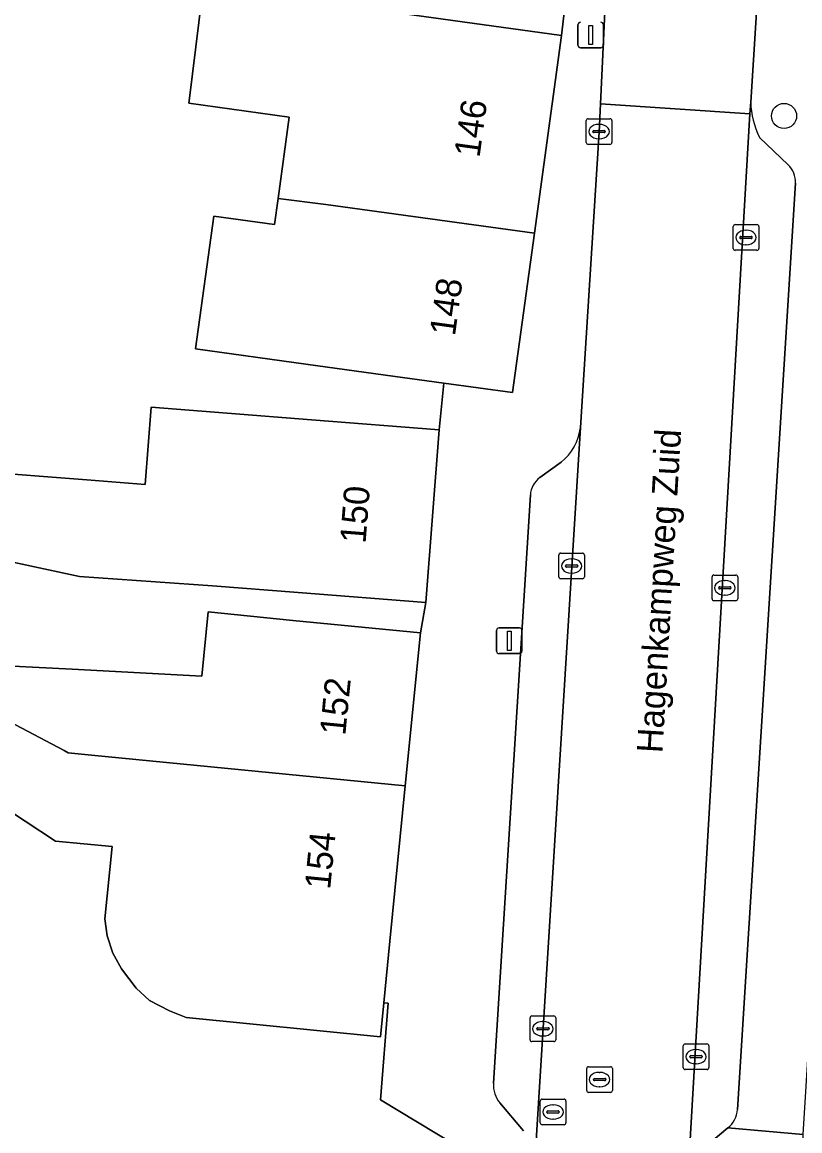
# Model space of a CAD drawing. Extents: x 160102 to 160934, y 382045 to 382923.
# Drawn here: x 160536.3 to 160566.62, y 382542.01 to 382585.21 of the extents above; entities that cross this region are included whole.
import ezdxf

# ---------------------------------------------------------------- set-up
doc = ezdxf.new("R2010")
doc.units = 0
for name, color, linetype in [('IMGEO_Boom', 7, 'Continuous'), ('IMGEO_Brandkraan', 7, 'Continuous'), ('IMGEO_Erf', 7, 'Continuous'), ('IMGEO_Kolk', 7, 'Continuous'), ('IMGEO_Lichtmast', 7, 'Continuous'), ('IMGEO_Openbare_ruimte_label', 7, 'Continuous'), ('IMGEO_Pand', 7, 'Continuous'), ('IMGEO_Pand_nummerreeks', 7, 'Continuous'), ('IMGEO_Parkeervlak_open', 7, 'Continuous'), ('IMGEO_Rijbaan_lokaal_open', 7, 'Continuous'), ('IMGEO_Rioolput', 7, 'Continuous'), ('IMGEO_Voetpad_open', 7, 'Continuous')]:
    doc.layers.add(name, color=color, linetype=linetype)

msp = doc.modelspace()

# ---------------------------------------------------------------- linework, layer by layer
at = {"layer": 'IMGEO_Boom'}
msp.add_circle((160566.008, 382581.561), 0.489, dxfattribs=at)
at = {"layer": 'IMGEO_Brandkraan'}
for p, q in [((160556.501, 382542.322), (160556.501, 382543.174)), ((160556.576, 382543.248), (160557.428, 382543.248)), ((160556.989, 382543.028), (160557.014, 382543.028)), ((160557.502, 382543.174), (160557.502, 382542.322)), ((160556.76, 382542.742), (160556.76, 382542.754)), ((160557.198, 382542.705), (160556.8, 382542.705)), ((160556.803, 382542.791), (160557.201, 382542.791)), ((160557.012, 382542.468), (160556.987, 382542.468)), ((160557.244, 382542.754), (160557.244, 382542.742)), ((160557.428, 382542.248), (160556.576, 382542.248))]:
    msp.add_line(p, q, dxfattribs=at)
for points in [[(160556.501, 382542.322), (160556.501, 382543.174)], [(160556.576, 382543.248), (160557.428, 382543.248)], [(160557.502, 382543.174), (160557.502, 382542.322)], [(160557.428, 382542.248), (160556.576, 382542.248)]]:
    msp.add_lwpolyline(points, dxfattribs=at)
for centre, radius, start, end in [((160556.578, 382543.172), 0.0765, 91.552, 178.448), ((160556.578, 382543.172), 0.0765, 91.552, 178.448), ((160557.426, 382543.172), 0.0765, 1.552, 88.448), ((160557.426, 382543.172), 0.0765, 1.552, 88.448), ((160556.8, 382542.751), 0.0403, 85.8775, 175.7526), ((160556.797, 382542.741), 0.0366, 178.938, 274.7102), ((160557.201, 382542.748), 0.043, 264.8664, 352.4533), ((160557.205, 382542.753), 0.0386, 1.7309, 96.639), ((160556.578, 382542.324), 0.0765, 181.552, 268.448), ((160556.578, 382542.324), 0.0765, 181.552, 268.448), ((160557.426, 382542.324), 0.0765, 271.552, 358.448), ((160557.426, 382542.324), 0.0765, 271.552, 358.448)]:
    msp.add_arc(centre, radius, start, end, dxfattribs=at)
for centre, major_axis, ratio, start_param, end_param in [((160556.988, 382542.748), (-0.387, 0.002), 0.722429, 4.712389, 7.853982), ((160557.013, 382542.748), (-0.39, 0.002), 0.717154, 1.570796, 4.712389)]:
    msp.add_ellipse(centre, major_axis=major_axis, ratio=ratio, start_param=start_param, end_param=end_param, dxfattribs=at)
at = {"layer": 'IMGEO_Erf'}
for points in [[(160534.423, 382567.722), (160538.823, 382567.379), (160541.092, 382567.202), (160541.327, 382570.206), (160544.296, 382569.974), (160547.58, 382569.718), (160552.564, 382569.329), (160552.74, 382571.149), (160550.464, 382571.463), (160547.358, 382571.891), (160543.062, 382572.483), (160543.774, 382577.654), (160546.137, 382577.329), (160546.277, 382578.344), (160546.714, 382581.519), (160542.799, 382582.058), (160542.826, 382582.251), (160544.031, 382592.059)], [(160553.83, 382590.868), (160553.333, 382590.898), (160550.367, 382591.268), (160550.341, 382591.08), (160549.608, 382585.762), (160557.335, 382584.697), (160557.538, 382586.493), (160556.132, 382586.617)], [(160534.372, 382560.203), (160538.255, 382559.998), (160543.303, 382559.732), (160543.549, 382562.231), (160546.852, 382561.905), (160551.827, 382561.414), (160552.04, 382562.601), (160547.056, 382562.989), (160543.727, 382563.248), (160538.538, 382563.615), (160535.938, 382564.173)], [(160554.602, 382540.614), (160550.277, 382543.226), (160550.574, 382546.994), (160550.406, 382547), (160550.275, 382545.677), (160542.701, 382546.424), (160542.048, 382546.688), (160541.272, 382547.092), (160540.742, 382547.567), (160540.177, 382548.324), (160539.842, 382548.94), (160539.612, 382549.61), (160539.529, 382550.277), (160539.806, 382553.087), (160537.595, 382553.305), (160532.862, 382556.422)]]:
    msp.add_lwpolyline(points, dxfattribs=at)
at = {"layer": 'IMGEO_Kolk'}
for p, q in [((160558.294, 382580.526), (160558.294, 382581.378)), ((160558.369, 382581.452), (160559.221, 382581.452)), ((160559.295, 382581.378), (160559.295, 382580.526)), ((160558.553, 382580.946), (160558.553, 382580.958)), ((160558.991, 382580.909), (160558.593, 382580.909)), ((160558.596, 382580.995), (160558.994, 382580.995)), ((160558.782, 382581.232), (160558.807, 382581.232)), ((160559.037, 382580.958), (160559.037, 382580.946)), ((160558.805, 382580.672), (160558.78, 382580.672)), ((160559.221, 382580.452), (160558.369, 382580.452)), ((160564.024, 382576.398), (160564.024, 382577.25)), ((160564.099, 382577.324), (160564.951, 382577.324)), ((160564.512, 382577.104), (160564.537, 382577.104)), ((160565.025, 382577.25), (160565.025, 382576.398)), ((160564.283, 382576.818), (160564.283, 382576.83)), ((160564.721, 382576.781), (160564.323, 382576.781)), ((160564.326, 382576.867), (160564.724, 382576.867)), ((160564.767, 382576.83), (160564.767, 382576.818)), ((160564.951, 382576.324), (160564.099, 382576.324)), ((160564.535, 382576.544), (160564.51, 382576.544)), ((160557.3, 382564.524), (160558.152, 382564.524)), ((160557.225, 382563.598), (160557.225, 382564.45)), ((160557.527, 382564.067), (160557.925, 382564.067)), ((160557.713, 382564.304), (160557.738, 382564.304)), ((160558.226, 382564.45), (160558.226, 382563.598)), ((160557.484, 382564.018), (160557.484, 382564.03)), ((160557.922, 382563.981), (160557.524, 382563.981)), ((160557.736, 382563.744), (160557.711, 382563.744)), ((160557.968, 382564.03), (160557.968, 382564.018)), ((160563.274, 382563.672), (160564.126, 382563.672)), ((160558.152, 382563.524), (160557.3, 382563.524)), ((160563.199, 382562.746), (160563.199, 382563.598)), ((160563.501, 382563.215), (160563.899, 382563.215)), ((160563.687, 382563.452), (160563.712, 382563.452)), ((160564.2, 382563.598), (160564.2, 382562.746)), ((160563.458, 382563.166), (160563.458, 382563.178)), ((160563.896, 382563.129), (160563.498, 382563.129)), ((160563.71, 382562.892), (160563.685, 382562.892)), ((160563.942, 382563.178), (160563.942, 382563.166)), ((160564.126, 382562.672), (160563.274, 382562.672)), ((160556.105, 382545.563), (160556.105, 382546.415)), ((160556.18, 382546.489), (160557.032, 382546.489)), ((160557.106, 382546.415), (160557.106, 382545.563)), ((160556.364, 382545.983), (160556.364, 382545.995)), ((160556.802, 382545.946), (160556.404, 382545.946)), ((160556.407, 382546.032), (160556.805, 382546.032)), ((160556.593, 382546.269), (160556.618, 382546.269)), ((160556.848, 382545.995), (160556.848, 382545.983)), ((160557.032, 382545.489), (160556.18, 382545.489)), ((160556.616, 382545.709), (160556.591, 382545.709)), ((160562.074, 382544.475), (160562.074, 382545.327)), ((160562.149, 382545.401), (160563.001, 382545.401)), ((160562.562, 382545.181), (160562.587, 382545.181)), ((160563.075, 382545.327), (160563.075, 382544.475)), ((160562.333, 382544.895), (160562.333, 382544.907)), ((160562.771, 382544.858), (160562.373, 382544.858)), ((160562.376, 382544.944), (160562.774, 382544.944)), ((160562.585, 382544.621), (160562.56, 382544.621)), ((160562.817, 382544.907), (160562.817, 382544.895)), ((160563.001, 382544.401), (160562.149, 382544.401))]:
    msp.add_line(p, q, dxfattribs=at)
for points in [[(160558.294, 382580.526), (160558.294, 382581.378)], [(160558.369, 382581.452), (160559.221, 382581.452)], [(160559.295, 382581.378), (160559.295, 382580.526)], [(160559.221, 382580.452), (160558.369, 382580.452)], [(160564.024, 382576.398), (160564.024, 382577.25)], [(160564.099, 382577.324), (160564.951, 382577.324)], [(160565.025, 382577.25), (160565.025, 382576.398)], [(160564.951, 382576.324), (160564.099, 382576.324)], [(160557.3, 382564.524), (160558.152, 382564.524)], [(160557.225, 382563.598), (160557.225, 382564.45)], [(160558.226, 382564.45), (160558.226, 382563.598)], [(160563.274, 382563.672), (160564.126, 382563.672)], [(160558.152, 382563.524), (160557.3, 382563.524)], [(160563.199, 382562.746), (160563.199, 382563.598)], [(160564.2, 382563.598), (160564.2, 382562.746)], [(160564.126, 382562.672), (160563.274, 382562.672)], [(160556.105, 382545.563), (160556.105, 382546.415)], [(160556.18, 382546.489), (160557.032, 382546.489)], [(160557.106, 382546.415), (160557.106, 382545.563)], [(160557.032, 382545.489), (160556.18, 382545.489)], [(160562.074, 382544.475), (160562.074, 382545.327)], [(160562.149, 382545.401), (160563.001, 382545.401)], [(160563.075, 382545.327), (160563.075, 382544.475)], [(160563.001, 382544.401), (160562.149, 382544.401)]]:
    msp.add_lwpolyline(points, dxfattribs=at)
for centre, radius, start, end in [((160558.371, 382581.376), 0.0765, 91.552, 178.448), ((160558.371, 382581.376), 0.0765, 91.552, 178.448), ((160559.219, 382581.376), 0.0765, 1.552, 88.448), ((160559.219, 382581.376), 0.0765, 1.552, 88.448), ((160558.593, 382580.955), 0.0403, 85.8775, 175.7526), ((160558.59, 382580.945), 0.0366, 178.938, 274.7102), ((160558.994, 382580.952), 0.043, 264.8664, 352.4533), ((160558.998, 382580.957), 0.0386, 1.7309, 96.639), ((160558.371, 382580.528), 0.0765, 181.552, 268.448), ((160558.371, 382580.528), 0.0765, 181.552, 268.448), ((160559.219, 382580.528), 0.0765, 271.552, 358.448), ((160559.219, 382580.528), 0.0765, 271.552, 358.448), ((160564.101, 382577.248), 0.0765, 91.552, 178.448), ((160564.101, 382577.248), 0.0765, 91.552, 178.448), ((160564.949, 382577.248), 0.0765, 1.552, 88.448), ((160564.949, 382577.248), 0.0765, 1.552, 88.448), ((160564.323, 382576.827), 0.0403, 85.8775, 175.7526), ((160564.32, 382576.817), 0.0366, 178.938, 274.7102), ((160564.724, 382576.824), 0.043, 264.8664, 352.4533), ((160564.728, 382576.829), 0.0386, 1.7309, 96.639), ((160564.101, 382576.4), 0.0765, 181.552, 268.448), ((160564.101, 382576.4), 0.0765, 181.552, 268.448), ((160564.949, 382576.4), 0.0765, 271.552, 358.448), ((160564.949, 382576.4), 0.0765, 271.552, 358.448), ((160557.302, 382564.448), 0.0765, 91.552, 178.448), ((160557.302, 382564.448), 0.0765, 91.552, 178.448), ((160558.15, 382564.448), 0.0765, 1.552, 88.448), ((160558.15, 382564.448), 0.0765, 1.552, 88.448), ((160557.524, 382564.027), 0.0403, 85.8775, 175.7526), ((160557.929, 382564.029), 0.0386, 1.7309, 96.639), ((160557.521, 382564.017), 0.0366, 178.938, 274.7102), ((160557.925, 382564.024), 0.043, 264.8664, 352.4533), ((160563.276, 382563.596), 0.0765, 91.552, 178.448), ((160563.276, 382563.596), 0.0765, 91.552, 178.448), ((160564.124, 382563.596), 0.0765, 1.552, 88.448), ((160564.124, 382563.596), 0.0765, 1.552, 88.448), ((160557.302, 382563.6), 0.0765, 181.552, 268.448), ((160557.302, 382563.6), 0.0765, 181.552, 268.448), ((160558.15, 382563.6), 0.0765, 271.552, 358.448), ((160558.15, 382563.6), 0.0765, 271.552, 358.448), ((160563.498, 382563.175), 0.0403, 85.8775, 175.7526), ((160563.903, 382563.177), 0.0386, 1.7309, 96.639), ((160563.495, 382563.165), 0.0366, 178.938, 274.7102), ((160563.899, 382563.172), 0.043, 264.8664, 352.4533), ((160563.276, 382562.748), 0.0765, 181.552, 268.448), ((160563.276, 382562.748), 0.0765, 181.552, 268.448), ((160564.124, 382562.748), 0.0765, 271.552, 358.448), ((160564.124, 382562.748), 0.0765, 271.552, 358.448), ((160556.182, 382546.413), 0.0765, 91.552, 178.448), ((160556.182, 382546.413), 0.0765, 91.552, 178.448), ((160557.03, 382546.413), 0.0765, 1.552, 88.448), ((160557.03, 382546.413), 0.0765, 1.552, 88.448), ((160556.404, 382545.992), 0.0403, 85.8775, 175.7526), ((160556.401, 382545.982), 0.0366, 178.938, 274.7102), ((160556.805, 382545.989), 0.043, 264.8664, 352.4533), ((160556.809, 382545.994), 0.0386, 1.7309, 96.639), ((160556.182, 382545.565), 0.0765, 181.552, 268.448), ((160556.182, 382545.565), 0.0765, 181.552, 268.448), ((160557.03, 382545.565), 0.0765, 271.552, 358.448), ((160557.03, 382545.565), 0.0765, 271.552, 358.448), ((160562.151, 382545.325), 0.0765, 91.552, 178.448), ((160562.151, 382545.325), 0.0765, 91.552, 178.448), ((160562.999, 382545.325), 0.0765, 1.552, 88.448), ((160562.999, 382545.325), 0.0765, 1.552, 88.448), ((160562.373, 382544.904), 0.0403, 85.8775, 175.7526), ((160562.37, 382544.894), 0.0366, 178.938, 274.7102), ((160562.774, 382544.901), 0.043, 264.8664, 352.4533), ((160562.778, 382544.906), 0.0386, 1.7309, 96.639), ((160562.151, 382544.477), 0.0765, 181.552, 268.448), ((160562.151, 382544.477), 0.0765, 181.552, 268.448), ((160562.999, 382544.477), 0.0765, 271.552, 358.448), ((160562.999, 382544.477), 0.0765, 271.552, 358.448)]:
    msp.add_arc(centre, radius, start, end, dxfattribs=at)
for centre, major_axis, ratio, start_param, end_param in [((160558.781, 382580.952), (-0.387, 0.002), 0.722429, 4.712389, 7.853982), ((160558.806, 382580.952), (-0.39, 0.002), 0.717154, 1.570796, 4.712389), ((160564.511, 382576.824), (-0.387, 0.002), 0.722429, 4.712389, 7.853982), ((160564.536, 382576.824), (-0.39, 0.002), 0.717154, 1.570796, 4.712389), ((160557.712, 382564.024), (-0.387, 0.002), 0.722429, 4.712389, 7.853982), ((160557.737, 382564.024), (-0.39, 0.002), 0.717154, 1.570796, 4.712389), ((160563.686, 382563.172), (-0.387, 0.002), 0.722429, 4.712389, 7.853982), ((160563.711, 382563.172), (-0.39, 0.002), 0.717154, 1.570796, 4.712389), ((160556.592, 382545.989), (-0.387, 0.002), 0.722429, 4.712389, 7.853982), ((160556.617, 382545.989), (-0.39, 0.002), 0.717154, 1.570796, 4.712389), ((160562.561, 382544.901), (-0.387, 0.002), 0.722429, 4.712389, 7.853982), ((160562.586, 382544.901), (-0.39, 0.002), 0.717154, 1.570796, 4.712389)]:
    msp.add_ellipse(centre, major_axis=major_axis, ratio=ratio, start_param=start_param, end_param=end_param, dxfattribs=at)
at = {"layer": 'IMGEO_Lichtmast'}
for p, q in [((160557.973, 382584.315), (160557.973, 382585.115)), ((160557.973, 382585.115), (160557.973, 382584.315)), ((160558.963, 382585.115), (160558.963, 382584.315)), ((160558.963, 382584.315), (160558.963, 382585.115)), ((160558.863, 382584.215), (160558.073, 382584.215)), ((160558.073, 382584.215), (160558.863, 382584.215)), ((160554.799, 382560.71), (160554.799, 382561.51)), ((160554.799, 382561.51), (160554.799, 382560.71)), ((160554.899, 382561.61), (160555.689, 382561.61)), ((160555.689, 382561.61), (160554.899, 382561.61)), ((160555.789, 382561.51), (160555.789, 382560.71)), ((160555.789, 382560.71), (160555.789, 382561.51)), ((160555.689, 382560.61), (160554.899, 382560.61)), ((160554.899, 382560.61), (160555.689, 382560.61))]:
    msp.add_line(p, q, dxfattribs=at)
for points in [[(160558.393, 382585.09), (160558.543, 382585.09), (160558.543, 382584.34), (160558.393, 382584.34), (160558.393, 382585.09)], [(160555.219, 382561.485), (160555.369, 382561.485), (160555.369, 382560.735), (160555.219, 382560.735), (160555.219, 382561.485)]]:
    msp.add_lwpolyline(points, dxfattribs=at)
for centre, start, end in [((160558.073, 382585.115), 90, 180), ((160558.073, 382585.115), 90, 180), ((160558.863, 382585.115), 0, 90), ((160558.863, 382585.115), 360, 90), ((160558.073, 382584.315), 180, 270), ((160558.073, 382584.315), 180, 270), ((160558.863, 382584.315), 270, 0), ((160558.863, 382584.315), 270, 0), ((160554.899, 382561.51), 90, 180), ((160554.899, 382561.51), 90, 180), ((160555.689, 382561.51), 0, 90), ((160555.689, 382561.51), 360, 90), ((160554.899, 382560.71), 180, 270), ((160554.899, 382560.71), 180, 270), ((160555.689, 382560.71), 270, 0), ((160555.689, 382560.71), 270, 0)]:
    msp.add_arc(centre, 0.1, start, end, dxfattribs=at)
at = {"layer": 'IMGEO_Pand'}
for points in [[(160549.608, 382585.762), (160550.341, 382591.08), (160550.367, 382591.268), (160544.031, 382592.059), (160542.826, 382582.251), (160542.799, 382582.058), (160546.714, 382581.519), (160546.277, 382578.344), (160548.143, 382578.112), (160556.273, 382576.99), (160557.335, 382584.697)], [(160556.273, 382576.99), (160548.143, 382578.112), (160546.277, 382578.344), (160546.137, 382577.329), (160543.774, 382577.654), (160543.062, 382572.483), (160547.358, 382571.891), (160550.464, 382571.463), (160552.74, 382571.149), (160555.417, 382570.78)], [(160547.58, 382569.718), (160544.296, 382569.974), (160541.327, 382570.206), (160541.092, 382567.202), (160538.823, 382567.379), (160534.423, 382567.722), (160534.226, 382565.184), (160535.938, 382564.173), (160538.538, 382563.615), (160543.727, 382563.248), (160547.056, 382562.989), (160552.04, 382562.601), (160552.564, 382569.329)], [(160551.827, 382561.414), (160546.852, 382561.905), (160543.549, 382562.231), (160543.303, 382559.732), (160538.255, 382559.998), (160534.372, 382560.203), (160534.13, 382558.833), (160537.943, 382556.836), (160538.099, 382556.743), (160538.999, 382556.655), (160551.24, 382555.455)], [(160551.24, 382555.455), (160538.999, 382556.655), (160538.099, 382556.743), (160537.943, 382556.836), (160534.13, 382558.833), (160532.862, 382556.422), (160537.595, 382553.305), (160539.806, 382553.087), (160539.529, 382550.277), (160539.612, 382549.61), (160539.842, 382548.94), (160540.177, 382548.324), (160540.742, 382547.567), (160541.272, 382547.092), (160542.048, 382546.688), (160542.701, 382546.424), (160550.275, 382545.677), (160550.406, 382547), (160550.643, 382549.403)]]:
    msp.add_lwpolyline(points, close=True, dxfattribs=at)
at = {"layer": 'IMGEO_Parkeervlak_open'}
for points in [[(160564.707, 382582.094), (160564.68, 382581.638), (160562.258, 382540.108)], [(160566.168, 382579.658), (160565.046, 382580.726)], [(160564.192, 382542.847), (160566.451, 382578.939)], [(160556.291, 382540.798), (160558.072, 382569.42)], [(160557.316, 382568.071), (160556.487, 382567.467)], [(160556.116, 382566.791), (160554.676, 382543.869)], [(160554.93, 382543.102), (160555.849, 382542.013)], [(160562.995, 382541.44), (160563.817, 382542.125)]]:
    msp.add_lwpolyline(points, dxfattribs=at)
for centre, radius, start, end in [((160568.21, 382582.236), 3.506, 182.3229, 205.5129), ((160565.537, 382578.995), 0.916, 356.5236, 46.4458), ((160556.05, 382569.667), 2.037, 308.4262, 353.0399), ((160557.018, 382566.736), 0.904, 125.9812, 176.5014), ((160555.76, 382543.802), 1.086, 176.4802, 220.1654), ((160563.192, 382542.908), 1.002, 308.5907, 356.5154)]:
    msp.add_arc(centre, radius, start, end, dxfattribs=at)
at = {"layer": 'IMGEO_Rijbaan_lokaal_open'}
for points in [[(160559.252, 382590.336), (160559.2, 382589.486), (160558.845, 382582.037), (160564.68, 382581.638), (160564.707, 382582.094), (160565.209, 382589.942)], [(160556.271, 382540.489), (160562.258, 382540.108), (160564.68, 382581.638), (160558.845, 382582.037), (160558.793, 382580.934), (160558.072, 382569.42), (160556.291, 382540.798)]]:
    msp.add_lwpolyline(points, close=True, dxfattribs=at)
at = {"layer": 'IMGEO_Rioolput'}
for p, q in [((160558.314, 382543.586), (160558.314, 382544.438)), ((160558.389, 382544.512), (160559.241, 382544.512)), ((160558.802, 382544.292), (160558.827, 382544.292)), ((160559.315, 382544.438), (160559.315, 382543.586)), ((160558.573, 382544.006), (160558.573, 382544.018)), ((160559.011, 382543.969), (160558.613, 382543.969)), ((160558.616, 382544.055), (160559.014, 382544.055)), ((160559.057, 382544.018), (160559.057, 382544.006)), ((160559.241, 382543.512), (160558.389, 382543.512)), ((160558.825, 382543.732), (160558.8, 382543.732))]:
    msp.add_line(p, q, dxfattribs=at)
for points in [[(160558.314, 382543.586), (160558.314, 382544.438)], [(160558.389, 382544.512), (160559.241, 382544.512)], [(160559.315, 382544.438), (160559.315, 382543.586)], [(160559.241, 382543.512), (160558.389, 382543.512)]]:
    msp.add_lwpolyline(points, dxfattribs=at)
for centre, radius, start, end in [((160558.391, 382544.436), 0.0765, 91.552, 178.448), ((160558.391, 382544.436), 0.0765, 91.552, 178.448), ((160559.239, 382544.436), 0.0765, 1.552, 88.448), ((160559.239, 382544.436), 0.0765, 1.552, 88.448), ((160558.613, 382544.015), 0.0403, 85.8775, 175.7526), ((160558.61, 382544.005), 0.0366, 178.938, 274.7102), ((160559.014, 382544.012), 0.043, 264.8664, 352.4533), ((160559.018, 382544.017), 0.0386, 1.7309, 96.639), ((160558.391, 382543.588), 0.0765, 181.552, 268.448), ((160558.391, 382543.588), 0.0765, 181.552, 268.448), ((160559.239, 382543.588), 0.0765, 271.552, 358.448), ((160559.239, 382543.588), 0.0765, 271.552, 358.448)]:
    msp.add_arc(centre, radius, start, end, dxfattribs=at)
for centre, major_axis, ratio, start_param, end_param in [((160558.801, 382544.012), (-0.387, 0.002), 0.722429, 4.712389, 7.853982), ((160558.826, 382544.012), (-0.39, 0.002), 0.717154, 1.570796, 4.712389)]:
    msp.add_ellipse(centre, major_axis=major_axis, ratio=ratio, start_param=start_param, end_param=end_param, dxfattribs=at)
at = {"layer": 'IMGEO_Voetpad_open'}
for points in [[(160563.817, 382542.125), (160566.75, 382541.876), (160569.255, 382582.058), (160567.288, 382582.195), (160567.525, 382586.098), (160567.843, 382590.6), (160569.084, 382609.884)], [(160566.41, 382608.74), (160565.209, 382589.942), (160564.707, 382582.094)], [(160558.072, 382569.42), (160558.793, 382580.934), (160558.845, 382582.037), (160559.2, 382589.486)], [(160556.132, 382586.617), (160557.538, 382586.493), (160557.335, 382584.697), (160556.273, 382576.99), (160555.417, 382570.78), (160552.74, 382571.149), (160552.564, 382569.329), (160552.04, 382562.601), (160551.827, 382561.414), (160551.24, 382555.455), (160550.643, 382549.403), (160550.406, 382547), (160550.574, 382546.994), (160550.277, 382543.226), (160554.602, 382540.614), (160554.477, 382538.267), (160554.031, 382531.388), (160553.57, 382524.261), (160553.121, 382517.336), (160552.672, 382510.406), (160552.558, 382508.69), (160552.545, 382508.49), (160552.091, 382501.5)], [(160565.046, 382580.726), (160566.168, 382579.658)], [(160566.451, 382578.939), (160564.192, 382542.847)], [(160556.487, 382567.467), (160557.316, 382568.071)], [(160554.676, 382543.869), (160556.116, 382566.791)], [(160555.849, 382542.013), (160554.93, 382543.102)], [(160573.58, 382537.097), (160572.125, 382537.267), (160570.662, 382537.201), (160567.237, 382536.479), (160567.317, 382539.292), (160566.721, 382541.052), (160566.75, 382541.876), (160563.817, 382542.125), (160562.995, 382541.44)]]:
    msp.add_lwpolyline(points, dxfattribs=at)
for centre, radius, start, end in [((160568.21, 382582.236), 3.506, 182.3229, 205.5129), ((160565.537, 382578.995), 0.916, 356.5236, 46.4458), ((160556.05, 382569.667), 2.037, 308.4262, 353.0399), ((160557.018, 382566.736), 0.904, 125.9812, 176.5014), ((160555.76, 382543.802), 1.086, 176.4802, 220.1654), ((160563.192, 382542.908), 1.002, 308.5907, 356.5154)]:
    msp.add_arc(centre, radius, start, end, dxfattribs=at)

# ---------------------------------------------------------------- texts
at = {"layer": 'IMGEO_Openbare_ruimte_label'}
msp.add_text('Hagenkampweg Zuid', height=1, rotation=86.6739, dxfattribs=at).set_placement((160561.263, 382556.715))
at = {"layer": 'IMGEO_Pand_nummerreeks'}
for s, rotation, p in [('146', 82.1564, (160554.131, 382579.912)), ('148', 82.1517, (160553.174, 382572.958)), ('150', 85.5466, (160549.69, 382564.881)), ('152', 84.3738, (160548.899, 382557.398)), ('154', 84.368, (160548.308, 382551.395))]:
    msp.add_text(s, height=1, rotation=rotation, dxfattribs=at).set_placement(p)

doc.saveas('drawing.dxf')
